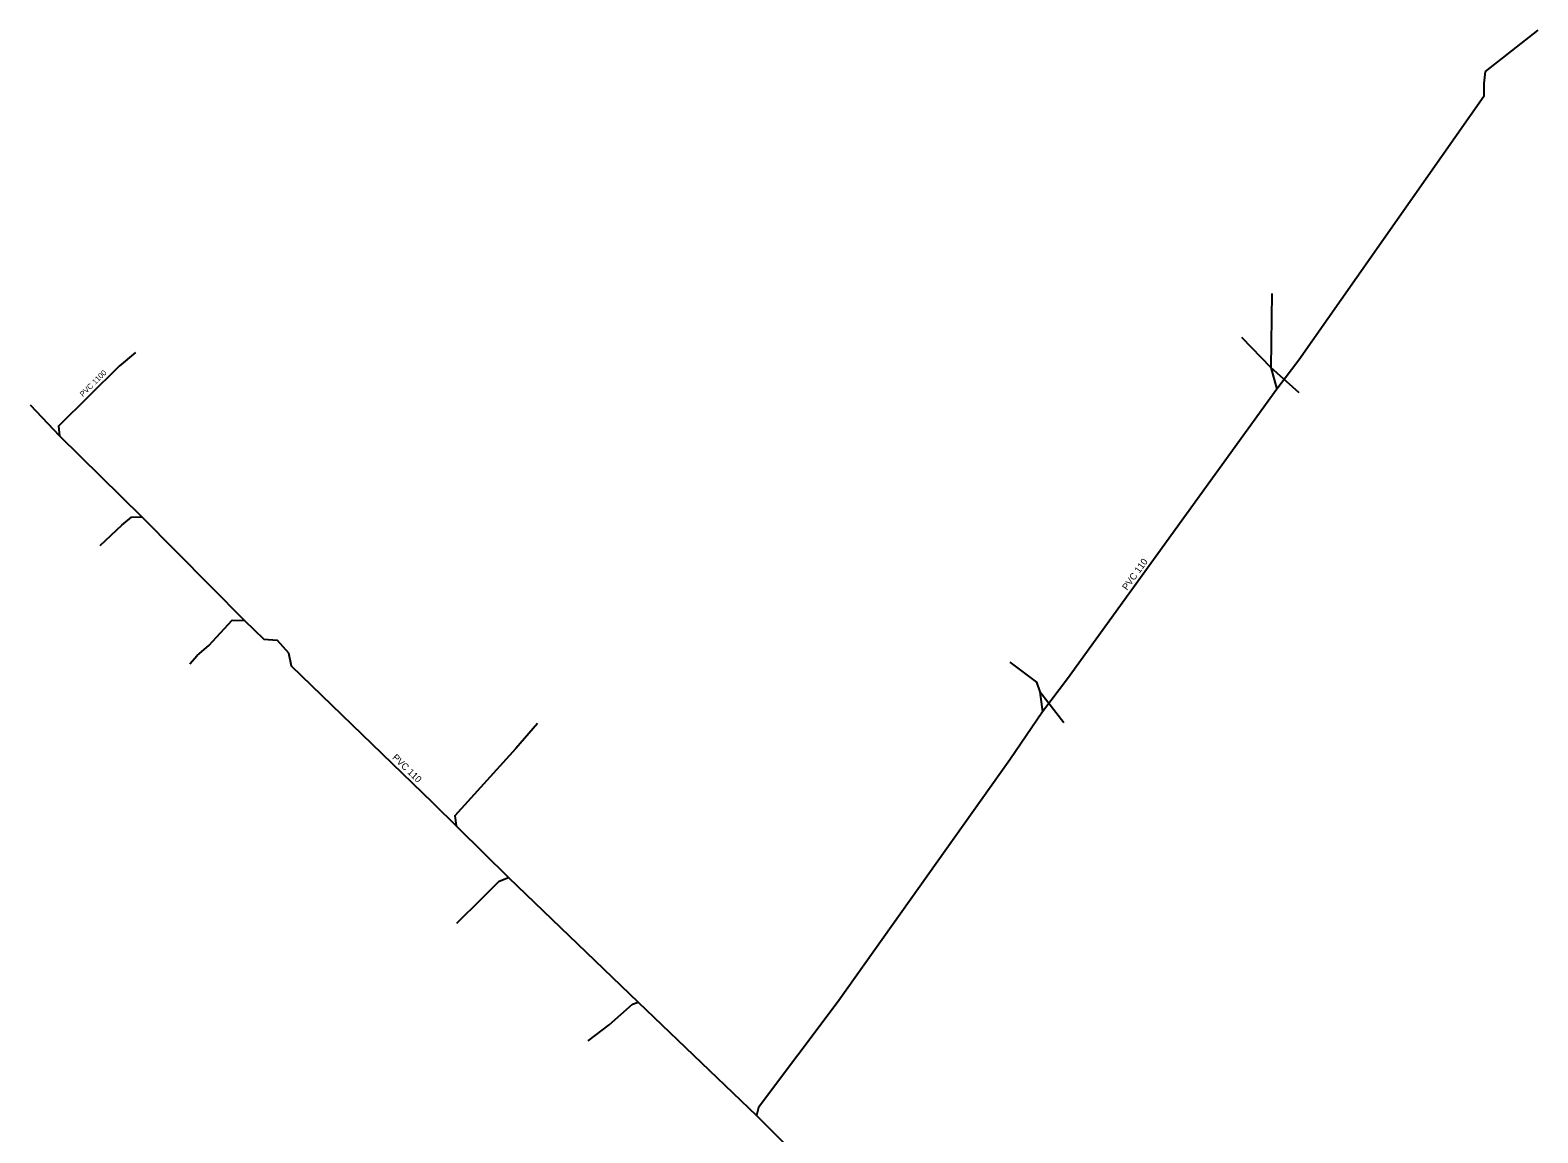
# Model space of a CAD drawing. Extents: x -687195 to -686827, y -1053873 to -1053627.
# Drawn here: x -687194.8 to -687082.8, y -1053733.1 to -1053651.3 of the extents above; entities that cross this region are included whole.
import ezdxf

# ---------------------------------------------------------------- set-up
doc = ezdxf.new("R2010")
doc.units = 0
for name, color, linetype in [('Kanalizační přípojky', 7, 'Continuous'), ('Kanalizační stoka', 7, 'Continuous'), ('Popis', 7, 'Continuous')]:
    doc.layers.add(name, color=color, linetype=linetype)

msp = doc.modelspace()

# ---------------------------------------------------------------- linework, layer by layer
at = {"layer": 'Kanalizační přípojky'}
for points in [[(-687082.83, -1053651.3), (-687086.73, -1053654.36)], [(-687102.59, -1053670.84), (-687102.65, -1053676.34)], [(-687104.83, -1053674.08), (-687102.65, -1053676.34)], [(-687186.95, -1053675.21), (-687188.17, -1053676.23)], [(-687188.17, -1053676.23), (-687192.66, -1053680.67), (-687192.58, -1053681.39)], [(-687100.55, -1053678.2), (-687102.65, -1053676.34)], [(-687102.65, -1053676.34), (-687102.2, -1053677.94)], [(-687189.58, -1053689.53), (-687187.97, -1053688.02)], [(-687187.97, -1053688.02), (-687187.25, -1053687.43), (-687186.49, -1053687.4)], [(-687181.51, -1053696.96), (-687179.76, -1053695.07), (-687178.85, -1053695.1)], [(-687182.91, -1053698.32), (-687182.37, -1053697.71), (-687181.5, -1053696.96)], [(-687122.03, -1053698.19), (-687120.06, -1053699.67), (-687119.8, -1053700.39)], [(-687119.8, -1053700.39), (-687119.61, -1053701.89)], [(-687118.02, -1053702.69), (-687119.8, -1053700.39)], [(-687157.11, -1053702.75), (-687158.7, -1053704.59)], [(-687158.7, -1053704.59), (-687163.25, -1053709.59), (-687163.15, -1053710.32)], [(-687161.23, -1053715.73), (-687159.96, -1053714.43), (-687159.26, -1053714.16)], [(-687163.08, -1053717.57), (-687161.23, -1053715.73)], [(-687151.79, -1053725.1), (-687150.05, -1053723.56), (-687149.62, -1053723.43)], [(-687153.35, -1053726.28), (-687151.79, -1053725.1)]]:
    msp.add_lwpolyline(points, dxfattribs=at)
at = {"layer": 'Kanalizační stoka'}
for points in [[(-687086.73, -1053654.36), (-687086.84, -1053655.26), (-687086.84, -1053656.22), (-687100.58, -1053675.78), (-687102.2, -1053677.94), (-687117.75, -1053699.44), (-687119.61, -1053701.89), (-687122.04, -1053705.44), (-687134.86, -1053723.48), (-687140.69, -1053731.24)], [(-687194.77, -1053679.11), (-687192.58, -1053681.39), (-687186.49, -1053687.4), (-687178.85, -1053695.1), (-687177.41, -1053696.48), (-687176.44, -1053696.56), (-687175.59, -1053697.5), (-687175.38, -1053698.46), (-687164.89, -1053708.6), (-687159.26, -1053714.16), (-687149.62, -1053723.43), (-687140.83, -1053731.84)], [(-687140.69, -1053731.24), (-687140.83, -1053731.84)], [(-687140.83, -1053731.84), (-687134.99, -1053737.63), (-687125.04, -1053747.71), (-687124.62, -1053748)]]:
    msp.add_lwpolyline(points, dxfattribs=at)

# ---------------------------------------------------------------- texts
at = {"layer": 'Popis'}
for s, height, rotation, p in [('PVC 1100', 0.4, 44.6792, (-687190.85, -1053678.53)), ('PVC 110', 0.5, 54.1234, (-687113.33, -1053692.9)), ('PVC 110', 0.5, 315.972, (-687167.92, -1053705.32))]:
    msp.add_text(s, height=height, rotation=rotation, dxfattribs=at).set_placement(p)

doc.saveas('drawing.dxf')
